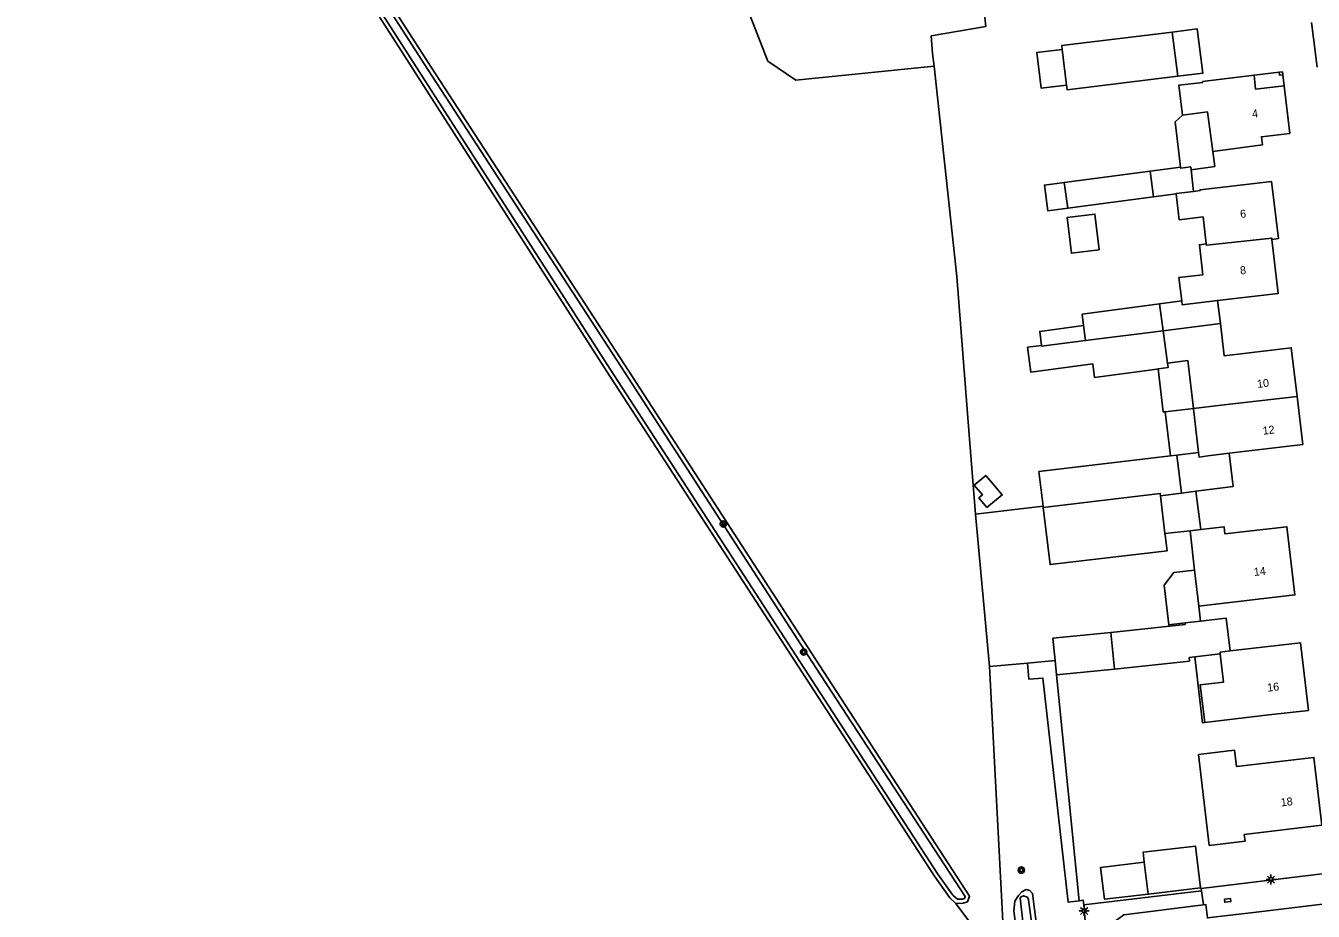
# Model space of a CAD drawing. Extents: x 140000 to 143000, y 403500 to 406000.
# Drawn here: x 140273.9 to 140434.8, y 403674.1 to 403784.8 of the extents above; entities that cross this region are included whole.
import ezdxf

# ---------------------------------------------------------------- set-up
doc = ezdxf.new("R2010")
doc.units = 0
for name, color, linetype in [('gg-afsc-erfafscheiding', 7, 'Continuous'), ('gg-afsc-hekwerk', 7, 'Continuous'), ('gg-anno-huisnummerreeks BGT', 7, 'Continuous'), ('gg-bbg-bijgebouw', 7, 'Continuous'), ('gg-bbg-gedigitaliseerde bebouwing', 7, 'Continuous'), ('gg-bbg-gedigitaliseerde bijgebouw', 7, 'Continuous'), ('gg-bbg-hoofdgebouw', 7, 'Continuous'), ('gg-bbg-luifel en loopbrug', 7, 'Continuous'), ('gg-bbg-onder overbouw', 7, 'Continuous'), ('gg-bbg-overig bouwwerk', 7, 'Continuous'), ('gg-bbg-pand overbouw', 7, 'Continuous'), ('gg-bbg-pilaar onder overbouw', 7, 'Continuous'), ('gg-bbg-pilaar pand', 7, 'Continuous'), ('gg-bbg-tussenscheiding', 7, 'Continuous'), ('gg-knt-verharding', 7, 'Continuous'), ('gg-kntw-bovenkant insteek waterloop', 7, 'Continuous'), ('gg-kntw-waterlijn', 7, 'Continuous'), ('gt-grn-groengrens', 7, 'Continuous'), ('gt-symb-boom', 7, 'Continuous'), ('gt-symb-kolk center center', 7, 'Continuous'), ('gt-symb-lichtmast', 7, 'Continuous')]:
    doc.layers.add(name, color=color, linetype=linetype)

# ---------------------------------------------------------------- blocks, each defined once
blk = doc.blocks.new('gt0-BOOM')
at = {"layer": 'gt-symb-boom'}
for radius in [0.4, 0.2]:
    blk.add_circle((0, 0), radius, dxfattribs=at)
blk = doc.blocks.new('gt0-KOLKCC')
at = {"layer": 'gt-symb-kolk center center'}
blk.add_lwpolyline([(-0.37, 0.2), (0.38, 0.2), (0.38, -0.2), (-0.37, -0.2)], close=True, dxfattribs=at)
blk = doc.blocks.new('gt0-LMAST')
at = {"layer": 'gt-symb-lichtmast'}
for p, q in [((-0.18, 0.17), (-0.45, 0.44)), ((-0.01, 0.25), (-0.01, 0.62)), ((0.17, 0.17), (0.44, 0.44)), ((-0.26, 0), (-0.63, 0)), ((-0.18, -0.18), (-0.45, -0.45)), ((-0.01, -0.25), (-0.01, -0.63)), ((0.44, -0.45), (0.17, -0.18)), ((0.24, 0), (0.62, 0))]:
    blk.add_line(p, q, dxfattribs=at)
blk.add_circle((-0.01, 0), 0.25, dxfattribs=at)

msp = doc.modelspace()

# ---------------------------------------------------------------- linework, layer by layer
at = {"layer": 'gg-afsc-erfafscheiding'}
msp.add_line((140399.08, 403705.11), (140394.31, 403704.68), dxfattribs=at)
for points in [[(140394.31, 403704.68), (140392.58, 403723.73), (140391.8, 403733.64), (140390.24, 403753.43), (140387.39, 403779.73)], [(140406.1, 403674.88), (140406.04, 403675.45), (140405.53, 403675.39)]]:
    msp.add_lwpolyline(points, dxfattribs=at)
at = {"layer": 'gg-afsc-hekwerk'}
for p, q in [((140387.21, 403781.33), (140387.39, 403779.73)), ((140387.39, 403779.73), (140390.24, 403753.43)), ((140392.58, 403723.73), (140401.03, 403724.72)), ((140392.58, 403723.73), (140394.31, 403704.68)), ((140394.31, 403704.68), (140399.08, 403705.11)), ((140402.69, 403703.65), (140405.53, 403675.39)), ((140405.53, 403675.39), (140406.04, 403675.45))]:
    msp.add_line(p, q, dxfattribs=at)
for points in [[(140387.05, 403783.52), (140393.86, 403784.67), (140389.01, 403829.61), (140390.49, 403829.8)], [(140390.24, 403753.43), (140391.8, 403733.64), (140392.58, 403723.73)]]:
    msp.add_lwpolyline(points, dxfattribs=at)
at = {"layer": 'gg-bbg-bijgebouw'}
for p, q in [((140417.17, 403783.99), (140417.85, 403778.46)), ((140403.96, 403777.36), (140403.41, 403781.83)), ((140403.67, 403765.19), (140414.41, 403766.61)), ((140414.84, 403763.38), (140414.41, 403766.61)), ((140404.1, 403761.96), (140403.67, 403765.19)), ((140414.84, 403763.38), (140404.1, 403761.96)), ((140416.03, 403746.66), (140415.58, 403750.01)), ((140406.33, 403745.42), (140406.08, 403747.31)), ((140417.75, 403731.1), (140416.94, 403731)), ((140418.32, 403726.36), (140417.75, 403731.1)), ((140415.71, 403726.02), (140418.32, 403726.36)), ((140415.71, 403726.02), (140416.26, 403721.29)), ((140418.79, 403709.92), (140409.49, 403708.92)), ((140409.49, 403708.92), (140409.93, 403704.34))]:
    msp.add_line(p, q, dxfattribs=at)
for points in [[(140403.41, 403781.83), (140403.36, 403782.3), (140417.17, 403783.99)], [(140417.85, 403778.46), (140404.04, 403776.77), (140403.96, 403777.36)], [(140406.08, 403747.31), (140405.89, 403748.72), (140415.58, 403750.01)], [(140400.81, 403744.8), (140400.83, 403744.72), (140406.33, 403745.42)], [(140415.4, 403741.89), (140414.94, 403741.83), (140407.47, 403740.83), (140407.24, 403742.52), (140399.49, 403741.49), (140399.08, 403744.59), (140400.81, 403744.8)], [(140416.57, 403742.6), (140416.64, 403742.05), (140415.4, 403741.89)], [(140401.05, 403724.55), (140401.03, 403724.72), (140400.51, 403729.04), (140416.94, 403731)], [(140401.05, 403724.55), (140401.9, 403717.42), (140416.52, 403719.14), (140416.29, 403721.1), (140416.26, 403721.29)], [(140409.93, 403704.34), (140419.32, 403705.35), (140419.27, 403705.79)], [(140413.67, 403680.21), (140413.52, 403681.46), (140420.06, 403682.24), (140420.68, 403677.01), (140414.14, 403676.24)], [(140414.14, 403676.24), (140408.68, 403675.6), (140408.21, 403679.57), (140413.67, 403680.21)]]:
    msp.add_lwpolyline(points, dxfattribs=at)
at = {"layer": 'gg-bbg-gedigitaliseerde bebouwing'}
msp.add_lwpolyline([(140423.17, 403706.25), (140423.58, 403702.74), (140420.67, 403702.4), (140421.22, 403697.68)], dxfattribs=at)
at = {"layer": 'gg-bbg-gedigitaliseerde bijgebouw'}
for p, q in [((140420.7, 403710.35), (140418.77, 403710.12)), ((140418.79, 403709.92), (140418.77, 403710.12)), ((140419.98, 403705.87), (140419.27, 403705.79)), ((140419.98, 403705.87), (140423.17, 403706.25))]:
    msp.add_line(p, q, dxfattribs=at)
msp.add_lwpolyline([(140424.39, 403706.62), (140423.92, 403710.72), (140420.7, 403710.35)], dxfattribs=at)
at = {"layer": 'gg-bbg-hoofdgebouw'}
for p, q in [((140423.18, 403747.57), (140416.03, 403746.66)), ((140420.73, 403721.8), (140419.39, 403721.65)), ((140419.96, 403716.73), (140419.39, 403721.65)), ((140419.96, 403716.73), (140420.49, 403712.22))]:
    msp.add_line(p, q, dxfattribs=at)
for points in [[(140427.39, 403778.61), (140420.96, 403777.82), (140420.97, 403777.7), (140417.99, 403777.34), (140418.44, 403773.59)], [(140422.23, 403769.07), (140428.46, 403769.9), (140428.32, 403770.91), (140431.86, 403771.33), (140431.14, 403777.28)], [(140418.44, 403773.59), (140421.57, 403774.01), (140422.23, 403769.07)], [(140429.62, 403758.05), (140430.43, 403758.17), (140429.59, 403765.32), (140420.64, 403764.28), (140420.65, 403764.18), (140419.84, 403764.08)], [(140419.84, 403764.08), (140417.66, 403763.83), (140417.67, 403763.76)], [(140421.41, 403757.5), (140421.02, 403760.89), (140418.05, 403760.54), (140417.67, 403763.76)], [(140421.41, 403757.5), (140420.57, 403757.41), (140421.01, 403753.66), (140418.01, 403753.31), (140418.36, 403750.38)], [(140429.62, 403758.05), (140430.39, 403751.29), (140422.84, 403750.42)], [(140418.36, 403750.38), (140418.41, 403749.91), (140422.84, 403750.42)], [(140432.77, 403738.44), (140432.04, 403744.52), (140423.67, 403743.52), (140423.18, 403747.57)], [(140416.57, 403742.6), (140419.11, 403742.93), (140419.81, 403736.94)], [(140432.77, 403738.44), (140433.48, 403732.44), (140424.27, 403731.33)], [(140419.81, 403736.94), (140419.82, 403736.9), (140420.46, 403731.42)], [(140420.46, 403731.42), (140420.52, 403730.86), (140421.61, 403731.01), (140424.27, 403731.33)], [(140420.49, 403712.22), (140432.5, 403713.62), (140431.51, 403722.15), (140423.76, 403721.25), (140423.66, 403722.14), (140420.73, 403721.8)], [(140421.22, 403697.68), (140429.22, 403698.62), (140434.18, 403699.2), (140433.19, 403707.65), (140424.39, 403706.62)], [(140420.43, 403693.68), (140421.8, 403682.31), (140426.27, 403682.85), (140426.17, 403683.69), (140435.87, 403684.86), (140434.88, 403693.31), (140425.2, 403692.18), (140424.96, 403694.22), (140420.43, 403693.68)]]:
    msp.add_lwpolyline(points, dxfattribs=at)
at = {"layer": 'gg-bbg-luifel en loopbrug'}
for p, q in [((140418.03, 403768.56), (140418.2, 403767.1)), ((140414.41, 403766.61), (140418.2, 403767.1)), ((140419.84, 403764.08), (140419.52, 403766.79)), ((140417.67, 403763.76), (140414.84, 403763.38)), ((140418.36, 403750.38), (140415.58, 403750.01)), ((140423.18, 403747.57), (140422.84, 403750.42)), ((140419.81, 403736.94), (140416.29, 403736.53)), ((140416.94, 403731), (140416.29, 403736.53)), ((140420.46, 403731.42), (140417.75, 403731.1)), ((140418.32, 403726.36), (140420.12, 403726.59)), ((140420.73, 403721.8), (140420.12, 403726.59)), ((140419.39, 403721.65), (140416.26, 403721.29)), ((140420.7, 403710.35), (140420.49, 403712.22)), ((140402.52, 403705.44), (140402.69, 403703.65)), ((140409.93, 403704.34), (140402.69, 403703.65))]:
    msp.add_line(p, q, dxfattribs=at)
for points in [[(140417.17, 403783.99), (140420.29, 403784.38), (140420.97, 403778.85), (140417.85, 403778.46)], [(140403.96, 403777.36), (140400.79, 403776.97), (140400.24, 403781.44), (140403.41, 403781.83)], [(140418.44, 403773.59), (140417.52, 403772.76), (140418.03, 403768.56)], [(140419.52, 403766.79), (140422.48, 403767.2), (140422.23, 403769.07)], [(140418.2, 403767.1), (140418.22, 403766.98), (140419.48, 403767.13), (140419.52, 403766.79)], [(140408.04, 403756.77), (140407.5, 403761.23), (140404.02, 403760.81), (140404.56, 403756.34), (140408.04, 403756.77)], [(140400.81, 403744.8), (140400.61, 403746.58), (140406.08, 403747.31)], [(140415.4, 403741.89), (140416.04, 403736.5), (140416.29, 403736.53)], [(140424.27, 403731.33), (140424.77, 403727.19), (140420.12, 403726.59)], [(140418.77, 403710.12), (140416.73, 403709.88), (140416.15, 403714.85), (140417.37, 403716.43), (140419.96, 403716.73)], [(140409.49, 403708.92), (140402.25, 403708.22), (140402.52, 403705.44)], [(140421.22, 403697.68), (140420.94, 403697.65), (140419.98, 403705.87)]]:
    msp.add_lwpolyline(points, dxfattribs=at)
at = {"layer": 'gg-bbg-onder overbouw'}
msp.add_lwpolyline([(140431.14, 403777.28), (140427.59, 403776.85), (140427.39, 403778.61)], dxfattribs=at)
at = {"layer": 'gg-bbg-overig bouwwerk'}
for points in [[(140404.1, 403761.96), (140401.62, 403761.63), (140401.19, 403764.86), (140403.67, 403765.19)], [(140394.01, 403724.54), (140395.91, 403726.14), (140393.86, 403728.57), (140392.43, 403727.36), (140393.45, 403726.15), (140392.98, 403725.76), (140394.01, 403724.54)]]:
    msp.add_lwpolyline(points, dxfattribs=at)
at = {"layer": 'gg-bbg-pand overbouw'}
for p, q in [((140430.53, 403778.99), (140427.39, 403778.61)), ((140431.14, 403777.28), (140430.98, 403778.64))]:
    msp.add_line(p, q, dxfattribs=at)
at = {"layer": 'gg-bbg-pilaar onder overbouw'}
msp.add_lwpolyline([(140430.53, 403778.99), (140430.58, 403778.59), (140430.98, 403778.64)], dxfattribs=at)
at = {"layer": 'gg-bbg-pilaar pand'}
msp.add_lwpolyline([(140430.53, 403778.99), (140430.93, 403779.04), (140430.98, 403778.64)], dxfattribs=at)
at = {"layer": 'gg-bbg-tussenscheiding'}
for p, q in [((140416.03, 403746.66), (140406.33, 403745.42)), ((140416.03, 403746.66), (140416.57, 403742.6)), ((140413.67, 403680.21), (140414.14, 403676.24))]:
    msp.add_line(p, q, dxfattribs=at)
for points in [[(140421.41, 403757.5), (140421.43, 403757.35), (140429.6, 403758.23), (140429.62, 403758.05)], [(140419.81, 403736.94), (140423.29, 403737.34), (140432.77, 403738.44)], [(140401.05, 403724.55), (140415.67, 403726.32), (140415.71, 403726.02)], [(140424.39, 403706.62), (140423.14, 403706.47), (140423.17, 403706.25)]]:
    msp.add_lwpolyline(points, dxfattribs=at)
at = {"layer": 'gg-knt-verharding'}
for p, q in [((140399.08, 403705.11), (140402.52, 403705.44)), ((140405.53, 403675.39), (140402.69, 403703.65)), ((140420.84, 403676.64), (140406.1, 403674.88)), ((140421.06, 403674.9), (140420.84, 403676.64))]:
    msp.add_line(p, q, dxfattribs=at)
for points in [[(140390.49, 403829.8), (140389.01, 403829.61), (140393.86, 403784.67), (140387.05, 403783.52), (140387.21, 403781.33), (140387.39, 403779.73)], [(140435.27, 403779.59), (140434.84, 403783.25), (140434.58, 403785.19)], [(140405.53, 403675.39), (140404.15, 403675.24), (140401, 403703.24), (140399.24, 403703.1), (140399.08, 403705.11)], [(140420.84, 403676.64), (140420.8, 403676.92), (140441.72, 403679.45), (140442.4, 403680.22)], [(140421.06, 403674.9), (140421.35, 403674.93), (140421.56, 403673.25), (140428.02, 403674.03), (140433.53, 403674.69), (140451.73, 403676.87), (140452.21, 403677.54)], [(140406.1, 403674.88), (140407.67, 403655.99), (140419.56, 403619.22), (140419.42, 403615.9), (140420.91, 403607.91)], [(140428.35, 403580.45), (140426.79, 403594.18), (140424.99, 403595.96), (140421.18, 403616.33), (140421.45, 403619.53), (140409.47, 403656.48), (140408.2, 403671.5), (140411.12, 403673.65), (140421.06, 403674.9)]]:
    msp.add_lwpolyline(points, dxfattribs=at)
at = {"layer": 'gg-kntw-bovenkant insteek waterloop'}
for points in [[(140159.75, 404104.28), (140159.27, 404104.06), (140159.15, 404103.49), (140160.2, 404100.35), (140171.95, 404065.52), (140183.47, 404032.39), (140197.86, 403991.99), (140210.28, 403954.91), (140213.02, 403947.69), (140214.47, 403944.24), (140216.55, 403940.67), (140267.25, 403863.71), (140292.07, 403825.55), (140318.01, 403786.01), (140346.51, 403741.58), (140387.45, 403678.45), (140389.37, 403675.78), (140390.13, 403675.07)], [(140267.48, 403866.73), (140292.86, 403828.8), (140324.54, 403779.59), (140348.72, 403742.43), (140373.1, 403704.75), (140391.84, 403675.97), (140391.59, 403675.27), (140391.04, 403675.11), (140390.13, 403675.07)], [(140420.85, 403578.21), (140419.47, 403583.11), (140410.65, 403615.1), (140404.44, 403637.32), (140400.95, 403650.31), (140399.75, 403655.87), (140397.36, 403674.15), (140397.48, 403675.34), (140397.93, 403676.05), (140398.38, 403676.52), (140398.92, 403676.79), (140399.36, 403676.66), (140399.71, 403676.32), (140402.3, 403656.1), (140403.18, 403651.75), (140408.57, 403633.77), (140416, 403606.64)]]:
    msp.add_lwpolyline(points, dxfattribs=at)
at = {"layer": 'gg-kntw-waterlijn'}
for points in [[(140267.67, 403863.98), (140292.49, 403825.83), (140318.43, 403786.28), (140346.93, 403741.85), (140387.87, 403678.73), (140389.74, 403676.11), (140390.32, 403675.58), (140390.96, 403675.6), (140391.21, 403675.68), (140391.29, 403675.91), (140372.68, 403704.48), (140348.3, 403742.16), (140324.12, 403779.32), (140292.45, 403828.53), (140264.98, 403869.56)], [(140422.01, 403578.25), (140417.19, 403595.3), (140411.3, 403616.57), (140403.88, 403643.13), (140402.24, 403648.78), (140401.59, 403651.4), (140400.92, 403653.77), (140400.54, 403656.18), (140399.22, 403666.63), (140398.15, 403675.74), (140398.28, 403675.87), (140398.58, 403676.02), (140399.06, 403675.86), (140399.21, 403675.52), (140401.74, 403656.78), (140402, 403653.48), (140402.42, 403651.77), (140403.56, 403647.85), (140407.7, 403632.6), (140415.15, 403605.49), (140421.14, 403584.7), (140422.89, 403578.51)]]:
    msp.add_lwpolyline(points, dxfattribs=at)
at = {"layer": 'gt-grn-groengrens'}
for p, q in [((140394.31, 403704.68), (140396.32, 403666.76)), ((140396.32, 403666.76), (140390.13, 403675.07))]:
    msp.add_line(p, q, dxfattribs=at)
msp.add_lwpolyline([(140387.39, 403779.73), (140370.14, 403777.98), (140366.61, 403780.36), (140324.84, 403887.61), (140373.74, 403938.86), (140380.15, 403940.39)], dxfattribs=at)

# ---------------------------------------------------------------- block references
at = {"layer": 'gt-symb-boom'}
for p in [(140361.05, 403722.49), (140371.09, 403706.5), (140398.31, 403679.23)]:
    msp.add_blockref('gt0-BOOM', p, dxfattribs=at)
at = {"layer": 'gt-symb-kolk center center', "rotation": 5.398254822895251}
msp.add_blockref('gt0-KOLKCC', (140424.08, 403675.45), dxfattribs=at)
at = {"layer": 'gt-symb-lichtmast'}
for p in [(140429.52, 403678.04), (140406.16, 403674.13)]:
    msp.add_blockref('gt0-LMAST', p, dxfattribs=at)

# ---------------------------------------------------------------- texts
at = {"layer": 'gg-anno-huisnummerreeks BGT'}
for s, rotation, p in [('4', 6.9, (140427.2, 403773.28)), ('6', 6.7, (140425.71, 403760.74)), ('8', 6.5, (140425.7, 403753.68)), ('10', 6.7, (140427.83, 403739.5)), ('12', 6.8, (140428.53, 403733.65)), ('14', 6.6, (140427.42, 403715.99)), ('16', 6.6, (140429.1, 403701.53)), ('18', 6.6, (140430.79, 403687.18))]:
    msp.add_text(s, height=1, rotation=rotation, dxfattribs=at).set_placement(p)

doc.saveas('drawing.dxf')
